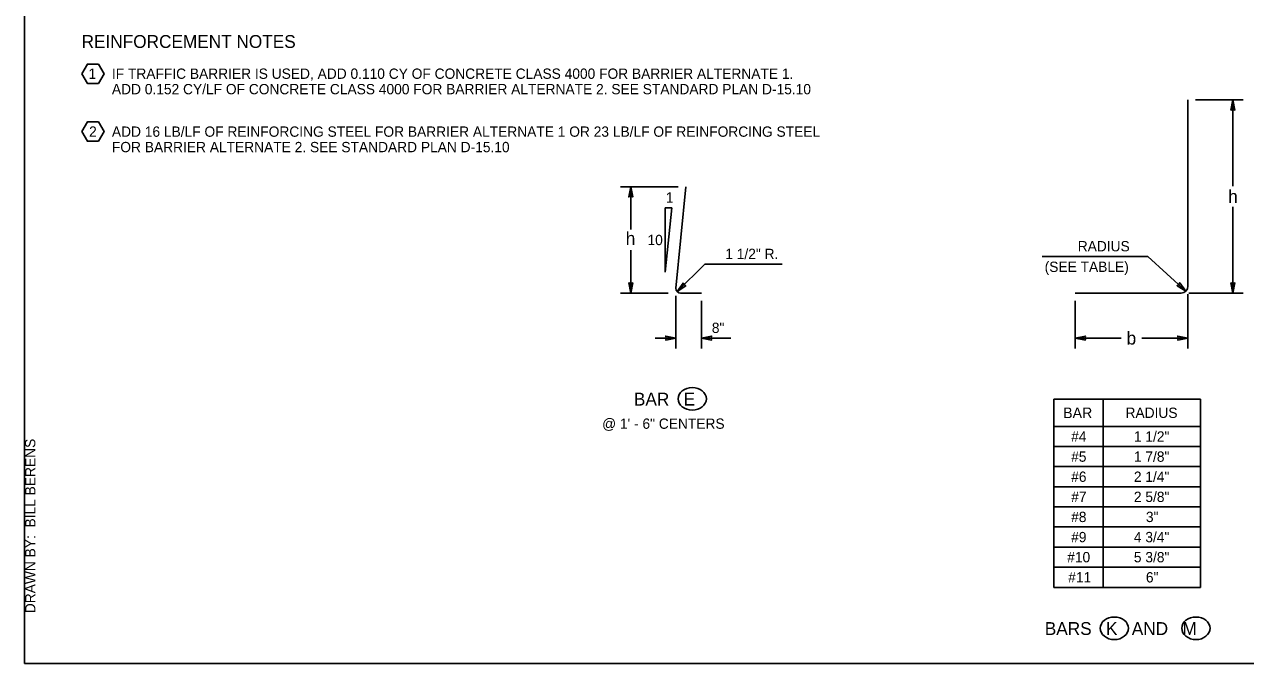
# Model space of a CAD drawing. Extents: x 99862 to 103151, y 100000 to 105076.
# Drawn here: x 99862 to 101760, y 103000 to 103992 of the extents above; entities that cross this region are included whole.
import ezdxf

# ---------------------------------------------------------------- set-up
doc = ezdxf.new("R2010")
doc.units = 0
for name, color, linetype in [('Level 1', 7, 'Continuous'), ('Level 15', 7, 'Continuous'), ('Level 20', 7, 'Continuous'), ('Level 21', 7, 'Continuous'), ('Level 4', 7, 'Continuous'), ('Level 5', 7, 'Continuous'), ('Level 60', 7, 'Continuous'), ('Level 62', 7, 'Continuous')]:
    doc.layers.add(name, color=color, linetype=linetype)

msp = doc.modelspace()

# ---------------------------------------------------------------- linework, layer by layer
at = {"layer": 'Level 1'}
msp.add_lwpolyline([(99862, 102999.5), (103151, 102999.5), (103151, 105075.5), (99862, 105075.5)], close=True, dxfattribs=at)
at = {"layer": 'Level 15'}
for p, q in [((101682.7, 103875.1), (101756.7, 103875.1)), ((101740.7, 103741.1), (101740.7, 103875.1)), ((100878.3, 103740.1), (100788.6, 103740.1)), ((100804.6, 103673.6), (100804.6, 103740.1)), ((100868.2, 103707.6), (100858.2, 103707.6)), ((100858.2, 103707.6), (100858.2, 103607.6)), ((100858.2, 103607.6), (100868.2, 103707.6)), ((101740.7, 103575.1), (101740.7, 103709.1)), ((100804.6, 103575.1), (100804.6, 103641.6)), ((101608.3, 103631.9), (101444.2, 103631.9)), ((101608.3, 103631.9), (101667.6, 103578.2)), ((100919.5, 103620), (100876.8, 103577.3)), ((100919.5, 103620), (101040.1, 103620)), ((100862.6, 103575.1), (100788.6, 103575.1)), ((101670.7, 103573.6), (101670.7, 103489.1)), ((101672.2, 103575.1), (101756.7, 103575.1)), ((100874.6, 103570.6), (100874.6, 103489.1)), ((100914.6, 103563.1), (100914.6, 103489.1)), ((101495.6, 103563.1), (101495.6, 103489.1)), ((100842.6, 103505.1), (100874.6, 103505.1)), ((100914.6, 103505.1), (100960.4, 103505.1)), ((101495.6, 103505.1), (101567.1, 103505.1)), ((101599.1, 103505.1), (101670.7, 103505.1))]:
    msp.add_line(p, q, dxfattribs=at)
for points in [[(101740.7, 103875.1), (101737.6, 103859.4), (101740.7, 103860.1), (101743.8, 103859.4)], [(101740.7, 103875.1), (101739.1, 103867.3), (101740.7, 103867.6), (101742.2, 103867.3)], [(100804.6, 103740.1), (100807.7, 103724.4), (100804.6, 103725.1), (100801.5, 103724.4)], [(100804.6, 103575.1), (100807.7, 103590.9), (100804.6, 103590.1), (100801.5, 103590.9)], [(100876.8, 103577.3), (100885.8, 103590.6), (100887.4, 103587.9), (100890.1, 103586.3)], [(101667.6, 103578.2), (101653.9, 103586.5), (101656.5, 103588.3), (101658, 103591)], [(101740.7, 103575.1), (101737.6, 103590.9), (101740.7, 103590.1), (101743.8, 103590.9)], [(101740.7, 103575.1), (101739.1, 103583), (101740.7, 103582.6), (101742.2, 103583)], [(100874.6, 103505.1), (100858.9, 103502.1), (100859.6, 103505.1), (100858.9, 103508.2)], [(100914.6, 103505.1), (100930.3, 103502.1), (100929.6, 103505.1), (100930.3, 103508.2)], [(101495.6, 103505.1), (101511.3, 103502.1), (101510.6, 103505.1), (101511.3, 103508.2)], [(101670.7, 103505.1), (101654.9, 103502.1), (101655.7, 103505.1), (101654.9, 103508.2)]]:
    msp.add_lwpolyline(points, close=True, dxfattribs=at)
at = {"layer": 'Level 20'}
for points in [[(99951.2, 103915.9), (99959.8, 103930.9), (99977.1, 103930.9), (99985.8, 103915.9), (99977.1, 103900.9), (99959.8, 103900.9), (99951.2, 103915.9)], [(99951.2, 103825.9), (99959.8, 103840.9), (99977.1, 103840.9), (99985.8, 103825.9), (99977.1, 103810.9), (99959.8, 103810.9), (99951.2, 103825.9)]]:
    msp.add_lwpolyline(points, dxfattribs=at)
for centre in [(100900.2, 103410.7), (101556.3, 103054.3), (101683.2, 103054.3)]:
    msp.add_ellipse(centre, major_axis=(-21.9, 0), ratio=0.8, dxfattribs=at)
at = {"layer": 'Level 4'}
for p, q in [((101462.5, 103410.3), (101690.5, 103410.3)), ((101462.5, 103410.3), (101462.5, 103117.9)), ((101539.1, 103410.3), (101539.1, 103117.9)), ((101690.5, 103410.3), (101690.5, 103117.9)), ((101462.5, 103367.9), (101690.5, 103367.9)), ((101462.5, 103336.7), (101690.5, 103336.7)), ((101462.5, 103305.4), (101690.5, 103305.4)), ((101462.5, 103274.2), (101690.5, 103274.2)), ((101462.5, 103242.9), (101690.5, 103242.9)), ((101462.5, 103211.7), (101690.5, 103211.7)), ((101462.5, 103180.4), (101690.5, 103180.4)), ((101462.5, 103149.2), (101690.5, 103149.2)), ((101462.5, 103117.9), (101690.5, 103117.9))]:
    msp.add_line(p, q, dxfattribs=at)
at = {"layer": 'Level 5'}
for p, q in [((101670.7, 103585.6), (101670.7, 103875.1)), ((100890.4, 103740.1), (100874.6, 103582.6)), ((100914.6, 103575.1), (100882.1, 103575.1)), ((101495.6, 103575.1), (101660.2, 103575.1))]:
    msp.add_line(p, q, dxfattribs=at)
for centre, radius, start, end in [((100882.1, 103582.6), 7.5, 180, 270), ((101660.2, 103585.6), 10.5, 270, 0)]:
    msp.add_arc(centre, radius, start, end, dxfattribs=at)
at = {"layer": 'Level 60'}
msp.add_line((99862, 102999.5), (99862, 102999.5), dxfattribs=at)

# ---------------------------------------------------------------- texts
at = {"layer": 'Level 20'}
for s, height, p in [('1', 16, (99961.6, 103907.9)), ('2', 16, (99962.5, 103817.9)), ('1', 16, (100859.1, 103715.6)), ('10', 16, (100830.6, 103649.6)), ('RADIUS', 16, (101499.4, 103639.9)), ('(SEE TABLE)', 16, (101448, 103607.9)), ('8"', 16, (100930.6, 103513.1)), ('b', 20, (101575.4, 103495.1)), ('BAR   E', 20, (100809.5, 103400.3)), ('BARS   K   AND   M', 20, (101448.2, 103043.9))]:
    msp.add_text(s, height=height, dxfattribs=at).set_placement(p)
for s, height, rotation, p in [('h', 20, 360, (101733.3, 103715.1)), ('h', 20, 360, (100796.8, 103650)), ('1 1/2" R.', 16, 359.9128, (100951.5, 103628))]:
    msp.add_text(s, height=height, rotation=rotation, dxfattribs=at).set_placement(p)
at = {"layer": 'Level 21'}
msp.add_text('@ 1\' - 6" CENTERS', height=16, dxfattribs=at).set_placement((100760.1, 103364.2))
at = {"layer": 'Level 4'}
for s, height, p in [('REINFORCEMENT NOTES', 20, (99950.9, 103955.9)), ('IF TRAFFIC BARRIER IS USED, ADD 0.110 CY OF CONCRETE CLASS 4000 FOR BARRIER ALTERNATE 1. ', 16, (99998, 103907.9)), ('ADD 0.152 CY/LF OF CONCRETE CLASS 4000 FOR BARRIER ALTERNATE 2. SEE STANDARD PLAN D-15.10', 16, (99998, 103883.9)), ('ADD 16 LB/LF OF REINFORCING STEEL FOR BARRIER ALTERNATE 1 OR 23 LB/LF OF REINFORCING STEEL', 16, (99998, 103817.9)), ('FOR BARRIER ALTERNATE 2. SEE STANDARD PLAN D-15.10', 16, (99998, 103793.9)), ('BAR', 16.5, (101476.7, 103380.8)), ('RADIUS', 16, (101573.7, 103381.1)), ('#4', 16, (101489.2, 103344.3)), ('1 1/2"', 16, (101586.7, 103344.3)), ('#5', 16, (101489.2, 103313)), ('1 7/8"', 16, (101586.7, 103313)), ('#6', 16, (101489.2, 103281.8)), ('2 1/4"', 16, (101586.7, 103281.8)), ('#7', 16, (101489.3, 103250.5)), ('2 5/8"', 16, (101586.7, 103250.5)), ('#8', 16, (101489.2, 103219.3)), ('3"', 16, (101605.4, 103219.3)), ('#9', 16, (101489.2, 103188)), ('4 3/4"', 16, (101586.7, 103188)), ('#10', 16, (101483.1, 103156.8)), ('5 3/8"', 16, (101586.7, 103156.8)), ('#11', 16, (101484.6, 103125.5)), ('6"', 16, (101605.4, 103125.5))]:
    msp.add_text(s, height=height, dxfattribs=at).set_placement(p)
at = {"layer": 'Level 62'}
msp.add_text('DRAWN BY:  BILL BERENS', height=16, rotation=90, dxfattribs=at).set_placement((99879, 103077.7))

doc.saveas('drawing.dxf')
